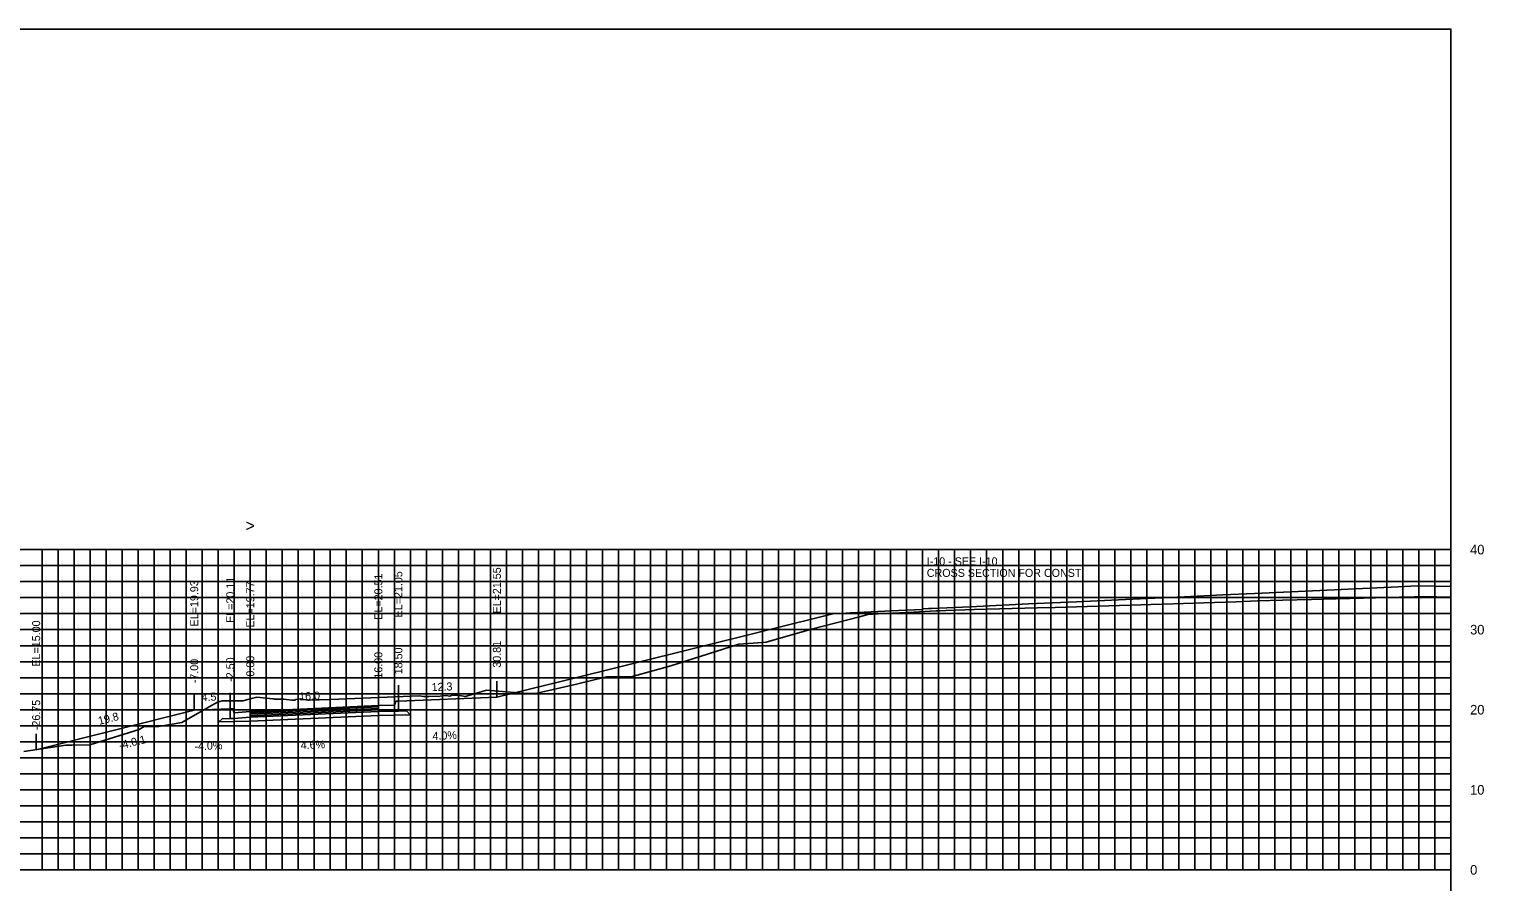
# Model space of a CAD drawing. Extents: x 1797652 to 1804159, y 242516 to 246906.
# Drawn here: x 1802956.9 to 1803138.6, y 242599.5 to 242706 of the extents above; entities that cross this region are included whole.
import ezdxf

# ---------------------------------------------------------------- set-up
doc = ezdxf.new("R2010")
doc.units = 0
for name, color, linetype in [('2', 7, 'Continuous'), ('3', 7, 'Continuous'), ('31', 7, 'Continuous'), ('4', 7, 'Continuous'), ('60', 7, 'Continuous'), ('BASE', 7, 'Continuous'), ('CL-CNST', 7, 'Continuous'), ('Level 62', 7, 'Continuous'), ('LOWER BINDER', 7, 'Continuous'), ('M-ROADS', 7, 'Continuous'), ('UPPER BINDER', 7, 'Continuous')]:
    doc.layers.add(name, color=color, linetype=linetype)

msp = doc.modelspace()

# ---------------------------------------------------------------- linework, layer by layer
for p, q in [((1803002.99, 242622.06), (1803002.99, 242624.06)), ((1803015.3, 242622.55), (1803015.3, 242624.55)), ((1802977.49, 242620.94), (1802977.49, 242622.94)), ((1802981.99, 242621.12), (1802981.99, 242623.12)), ((1802984.49, 242620.78), (1802984.49, 242622.78)), ((1803000.49, 242621.51), (1803000.49, 242623.51)), ((1802957.74, 242616), (1802957.74, 242618))]:
    msp.add_line(p, q)
for points in [[(1802834.49, 242516), (1803134.49, 242516), (1803134.49, 242706), (1802834.49, 242706)], [(1802984.49, 242620.78), (1802982.49, 242620.62), (1802982.32, 242621.12), (1802981.99, 242621.12), (1802981.98, 242619.89), (1802982.48, 242619.89), (1802984.49, 242620.06)], [(1803000.49, 242621.51), (1803002.49, 242621.56), (1803002.66, 242622.06), (1803002.99, 242622.06), (1803002.99, 242620.84), (1803002.49, 242620.84), (1803000.49, 242620.79)]]:
    msp.add_lwpolyline(points, close=True)
at = {"layer": '2'}
msp.add_lwpolyline([(1803000.49, 242621.36), (1803000.49, 242621.51), (1802984.49, 242620.78), (1802984.49, 242620.63)], close=True, dxfattribs=at)
at = {"layer": '60'}
for p, q in [((1803134.49, 242601), (1803134.49, 242641)), ((1803134.55, 242641), (1803134.49, 242641)), ((1803134.55, 242631), (1803134.49, 242631)), ((1803134.55, 242621), (1803134.49, 242621)), ((1803134.55, 242611), (1803134.49, 242611)), ((1802834.49, 242601), (1803134.49, 242601)), ((1802964.49, 242600.94), (1802964.49, 242601)), ((1802974.49, 242600.94), (1802974.49, 242601)), ((1802984.49, 242600.94), (1802984.49, 242601)), ((1802994.49, 242600.94), (1802994.49, 242601)), ((1803004.49, 242600.94), (1803004.49, 242601)), ((1803014.49, 242600.94), (1803014.49, 242601)), ((1803024.49, 242600.94), (1803024.49, 242601)), ((1803034.49, 242600.94), (1803034.49, 242601)), ((1803044.49, 242600.94), (1803044.49, 242601)), ((1803054.49, 242600.94), (1803054.49, 242601)), ((1803064.49, 242600.94), (1803064.49, 242601)), ((1803074.49, 242600.94), (1803074.49, 242601)), ((1803084.49, 242600.94), (1803084.49, 242601)), ((1803094.49, 242600.94), (1803094.49, 242601)), ((1803104.49, 242600.94), (1803104.49, 242601)), ((1803114.49, 242600.94), (1803114.49, 242601)), ((1803124.49, 242600.94), (1803124.49, 242601)), ((1803134.49, 242600.94), (1803134.49, 242601)), ((1803134.55, 242601), (1803134.49, 242601))]:
    msp.add_line(p, q, dxfattribs=at)
at = {"layer": 'BASE'}
msp.add_lwpolyline([(1802984.49, 242620.06), (1803000.49, 242620.79), (1803002.49, 242620.84), (1803002.99, 242620.84), (1803003.99, 242620.86), (1803004.47, 242620.38), (1803000.49, 242620.29), (1802984.49, 242619.56), (1802980.58, 242619.47), (1802980.98, 242619.87), (1802981.98, 242619.89), (1802982.48, 242619.89)], close=True, dxfattribs=at)
at = {"layer": 'CL-CNST'}
for points in [[(1803015.3, 242622.55), (1803023.28, 242624.53), (1803057.44, 242633.02), (1803058.89, 242633.08), (1803059.46, 242633.11), (1803065.49, 242633.39), (1803068.48, 242633.53), (1803068.51, 242633.56), (1803068.56, 242633.61), (1803069.21, 242633.63), (1803069.58, 242633.65), (1803074.43, 242633.87), (1803081.71, 242634.21), (1803087.73, 242634.49), (1803093.85, 242634.78), (1803101.19, 242635.12), (1803105.98, 242635.34), (1803109.95, 242635.52), (1803118.12, 242635.9), (1803127.92, 242636.36), (1803130.26, 242636.46), (1803134.49, 242636.37)], [(1802957.74, 242616), (1802977.49, 242620.94), (1802981.99, 242621.12), (1802982.32, 242621.12), (1802982.49, 242620.62), (1802984.49, 242620.78), (1803000.49, 242621.51), (1803002.49, 242621.56), (1803002.66, 242622.06), (1803002.99, 242622.06), (1803015.3, 242622.55)]]:
    msp.add_lwpolyline(points, dxfattribs=at)
at = {"layer": 'Level 62'}
for p, q in [((1802834.49, 242641), (1803134.49, 242641)), ((1802958.49, 242601), (1802958.49, 242641)), ((1802960.49, 242601), (1802960.49, 242641)), ((1802962.49, 242601), (1802962.49, 242641)), ((1802964.49, 242601), (1802964.49, 242641)), ((1802966.49, 242601), (1802966.49, 242641)), ((1802968.49, 242601), (1802968.49, 242641)), ((1802970.49, 242601), (1802970.49, 242641)), ((1802972.49, 242601), (1802972.49, 242641)), ((1802974.49, 242601), (1802974.49, 242641)), ((1802976.49, 242601), (1802976.49, 242641)), ((1802978.49, 242601), (1802978.49, 242641)), ((1802980.49, 242601), (1802980.49, 242641)), ((1802982.49, 242601), (1802982.49, 242641)), ((1802984.49, 242601), (1802984.49, 242641)), ((1802986.49, 242601), (1802986.49, 242641)), ((1802988.49, 242601), (1802988.49, 242641)), ((1802990.49, 242601), (1802990.49, 242641)), ((1802992.49, 242601), (1802992.49, 242641)), ((1802994.49, 242601), (1802994.49, 242641)), ((1802996.49, 242601), (1802996.49, 242641)), ((1802998.49, 242601), (1802998.49, 242641)), ((1803000.49, 242601), (1803000.49, 242641)), ((1803002.49, 242601), (1803002.49, 242641)), ((1803004.49, 242601), (1803004.49, 242641)), ((1803006.49, 242601), (1803006.49, 242641)), ((1803008.49, 242601), (1803008.49, 242641)), ((1803010.49, 242601), (1803010.49, 242641)), ((1803012.49, 242601), (1803012.49, 242641)), ((1803014.49, 242601), (1803014.49, 242641)), ((1803016.49, 242601), (1803016.49, 242641)), ((1803018.49, 242601), (1803018.49, 242641)), ((1803020.49, 242601), (1803020.49, 242641)), ((1803022.49, 242601), (1803022.49, 242641)), ((1803024.49, 242601), (1803024.49, 242641)), ((1803026.49, 242601), (1803026.49, 242641)), ((1803028.49, 242601), (1803028.49, 242641)), ((1803030.49, 242601), (1803030.49, 242641)), ((1803032.49, 242601), (1803032.49, 242641)), ((1803034.49, 242601), (1803034.49, 242641)), ((1803036.49, 242601), (1803036.49, 242641)), ((1803038.49, 242601), (1803038.49, 242641)), ((1803040.49, 242601), (1803040.49, 242641)), ((1803042.49, 242601), (1803042.49, 242641)), ((1803044.49, 242601), (1803044.49, 242641)), ((1803046.49, 242601), (1803046.49, 242641)), ((1803048.49, 242601), (1803048.49, 242641)), ((1803050.49, 242601), (1803050.49, 242641)), ((1803052.49, 242601), (1803052.49, 242641)), ((1803054.49, 242601), (1803054.49, 242641)), ((1803056.49, 242601), (1803056.49, 242641)), ((1803058.49, 242601), (1803058.49, 242641)), ((1803060.49, 242601), (1803060.49, 242641)), ((1803062.49, 242601), (1803062.49, 242641)), ((1803064.49, 242601), (1803064.49, 242641)), ((1803066.49, 242601), (1803066.49, 242641)), ((1803068.49, 242601), (1803068.49, 242641)), ((1803070.49, 242601), (1803070.49, 242641)), ((1803072.49, 242601), (1803072.49, 242641)), ((1803074.49, 242601), (1803074.49, 242641)), ((1803076.49, 242601), (1803076.49, 242641)), ((1803078.49, 242601), (1803078.49, 242641)), ((1803080.49, 242601), (1803080.49, 242641)), ((1803082.49, 242601), (1803082.49, 242641)), ((1803084.49, 242601), (1803084.49, 242641)), ((1803086.49, 242601), (1803086.49, 242641)), ((1803088.49, 242601), (1803088.49, 242641)), ((1803090.49, 242601), (1803090.49, 242641)), ((1803092.49, 242601), (1803092.49, 242641)), ((1803094.49, 242601), (1803094.49, 242641)), ((1803096.49, 242601), (1803096.49, 242641)), ((1803098.49, 242601), (1803098.49, 242641)), ((1803100.49, 242601), (1803100.49, 242641)), ((1803102.49, 242601), (1803102.49, 242641)), ((1803104.49, 242601), (1803104.49, 242641)), ((1803106.49, 242601), (1803106.49, 242641)), ((1803108.49, 242601), (1803108.49, 242641)), ((1803110.49, 242601), (1803110.49, 242641)), ((1803112.49, 242601), (1803112.49, 242641)), ((1803114.49, 242601), (1803114.49, 242641)), ((1803116.49, 242601), (1803116.49, 242641)), ((1803118.49, 242601), (1803118.49, 242641)), ((1803120.49, 242601), (1803120.49, 242641)), ((1803122.49, 242601), (1803122.49, 242641)), ((1803124.49, 242601), (1803124.49, 242641)), ((1803126.49, 242601), (1803126.49, 242641)), ((1803128.49, 242601), (1803128.49, 242641)), ((1803130.49, 242601), (1803130.49, 242641)), ((1803132.49, 242601), (1803132.49, 242641)), ((1803134.49, 242601), (1803134.49, 242641)), ((1802834.49, 242639), (1803134.49, 242639)), ((1802834.49, 242637), (1803134.49, 242637)), ((1802834.49, 242635), (1803134.49, 242635)), ((1802834.49, 242633), (1803134.49, 242633)), ((1802834.49, 242631), (1803134.49, 242631)), ((1802834.49, 242629), (1803134.49, 242629)), ((1802834.49, 242627), (1803134.49, 242627)), ((1802834.49, 242625), (1803134.49, 242625)), ((1802834.49, 242623), (1803134.49, 242623)), ((1802834.49, 242621), (1803134.49, 242621)), ((1802834.49, 242619), (1803134.49, 242619)), ((1802834.49, 242617), (1803134.49, 242617)), ((1802834.49, 242615), (1803134.49, 242615)), ((1802834.49, 242613), (1803134.49, 242613)), ((1802834.49, 242611), (1803134.49, 242611)), ((1802834.49, 242609), (1803134.49, 242609)), ((1802834.49, 242607), (1803134.49, 242607)), ((1802834.49, 242605), (1803134.49, 242605)), ((1802834.49, 242603), (1803134.49, 242603)), ((1802834.49, 242601), (1803134.49, 242601))]:
    msp.add_line(p, q, dxfattribs=at)
at = {"layer": 'LOWER BINDER'}
for points in [[(1802984.49, 242620.25), (1802984.49, 242620.44), (1803000.49, 242621.17), (1803000.49, 242620.98)], [(1802984.49, 242620.06), (1802984.49, 242620.25), (1803000.49, 242620.98), (1803000.49, 242620.79)]]:
    msp.add_lwpolyline(points, close=True, dxfattribs=at)
at = {"layer": 'M-ROADS'}
msp.add_lwpolyline([(1802956.22, 242615.77), (1802961.46, 242616.56), (1802962.25, 242616.57), (1802964.43, 242616.6), (1802970.6, 242618.55), (1802971.22, 242618.89), (1802971.73, 242618.89), (1802973.04, 242618.89), (1802975.94, 242619.41), (1802979.36, 242621.36), (1802980.4, 242621.94), (1802980.96, 242622.13), (1802981.27, 242622.1), (1802983.57, 242622.1), (1802984.8, 242622.44), (1802985.32, 242622.59), (1802987.29, 242622.36), (1802987.36, 242622.34), (1802987.48, 242622.38), (1802987.56, 242622.31), (1802988.6, 242622.3), (1802988.69, 242622.3), (1802989.7, 242622.21), (1802990.08, 242622.19), (1802990.16, 242622.29), (1802990.77, 242622.37), (1802991.7, 242622.19), (1802991.86, 242622.2), (1802993.01, 242622.23), (1802993.09, 242622.22), (1802994.56, 242622.28), (1803005.6, 242622.73), (1803006.16, 242622.65), (1803006.8, 242622.67), (1803007.58, 242622.71), (1803007.88, 242622.67), (1803008.5, 242622.75), (1803009.01, 242622.76), (1803009.4, 242622.7), (1803009.64, 242622.78), (1803010.18, 242622.8), (1803010.38, 242622.81), (1803011.36, 242622.67), (1803012.3, 242622.96), (1803013.48, 242623.26), (1803014.01, 242623.43), (1803017.52, 242623.16), (1803019.2, 242623.04), (1803020.34, 242623.06), (1803025.26, 242624.21), (1803028.98, 242625.1), (1803030.78, 242625.11), (1803032.08, 242625.12), (1803037.05, 242626.47), (1803045.54, 242629.18), (1803047.92, 242629.35), (1803048.94, 242629.42), (1803054.59, 242631.07), (1803060.59, 242632.61), (1803061.8, 242632.92), (1803062.24, 242632.94), (1803062.93, 242632.98), (1803067.38, 242633.2), (1803070.18, 242633.34), (1803070.7, 242633.37), (1803071.44, 242633.41), (1803074.91, 242633.51), (1803082.86, 242633.71), (1803085.04, 242633.78), (1803095.76, 242634.12), (1803096.99, 242634.16), (1803098.55, 242634.2), (1803103.64, 242634.36), (1803107.67, 242634.49), (1803110.32, 242634.58), (1803113.44, 242634.67), (1803117.06, 242634.78), (1803120.14, 242634.86), (1803123.58, 242634.93), (1803128.01, 242635.04), (1803129.94, 242635.09), (1803131.43, 242635.12), (1803131.75, 242635.12), (1803132.69, 242635.12), (1803134.49, 242635.05)], dxfattribs=at)
at = {"layer": 'UPPER BINDER'}
msp.add_lwpolyline([(1803000.49, 242621.17), (1803000.49, 242621.36), (1802984.49, 242620.63), (1802984.49, 242620.44)], close=True, dxfattribs=at)

# ---------------------------------------------------------------- texts
msp.add_text('-4.0:1', height=1, rotation=14.0362).set_placement((1802968.22, 242616.04))
at = {"layer": '3'}
for s, p in [('EL=21.55', (1803015.8, 242633.02)), ('EL=19.93', (1802977.99, 242631.41)), ('EL=20.11', (1802982.49, 242631.84)), ('EL=19.77', (1802984.99, 242631.25)), ('EL=20.51', (1803000.99, 242632.24)), ('EL=21.05', (1803003.49, 242632.53)), ('EL=15.00', (1802958.24, 242626.39)), ('30.81', (1803015.8, 242626.25)), ('0.00', (1802984.99, 242625.14)), ('16.00', (1803000.99, 242624.88)), ('18.50', (1803003.49, 242625.43)), ('-7.00', (1802977.99, 242624.31)), ('-2.50', (1802982.49, 242624.49)), ('-26.75', (1802958.24, 242618.45))]:
    msp.add_text(s, height=1, rotation=90, dxfattribs=at).set_placement(p)
for s, p in [('CROSS SECTION FOR CONST ', (1803069.01, 242637.59)), ('I-10 - SEE I-10', (1803069.01, 242639.03))]:
    msp.add_text(s, height=1, dxfattribs=at).set_placement(p)
at = {"layer": '31'}
for s, p in [('40', (1803136.89, 242640.4)), ('30', (1803136.89, 242630.4)), ('20', (1803136.89, 242620.4)), ('10', (1803136.89, 242610.4)), ('0', (1803136.89, 242600.4))]:
    msp.add_text(s, height=1.2, dxfattribs=at).set_placement(p)
at = {"layer": '4'}
for s, rotation, p in [('12.3', 2.2906, (1803007.16, 242623.32)), ('4.5', 2.2906, (1802978.42, 242622.07)), ('16.0', 2.6337, (1802990.62, 242622.16)), ('19.8', 14.0362, (1802965.62, 242619.1)), ('-4.0%', 2.2906, (1802977.53, 242615.93)), ('4.6%', 2.6337, (1802990.81, 242616.06)), ('4.0%', 2.2906, (1803007.27, 242617.22))]:
    msp.add_text(s, height=1, rotation=rotation, dxfattribs=at).set_placement(p)
at = {"layer": '60'}
msp.add_text('>', height=1.5, dxfattribs=at).set_placement((1802983.88, 242643.25))

doc.saveas('drawing.dxf')
